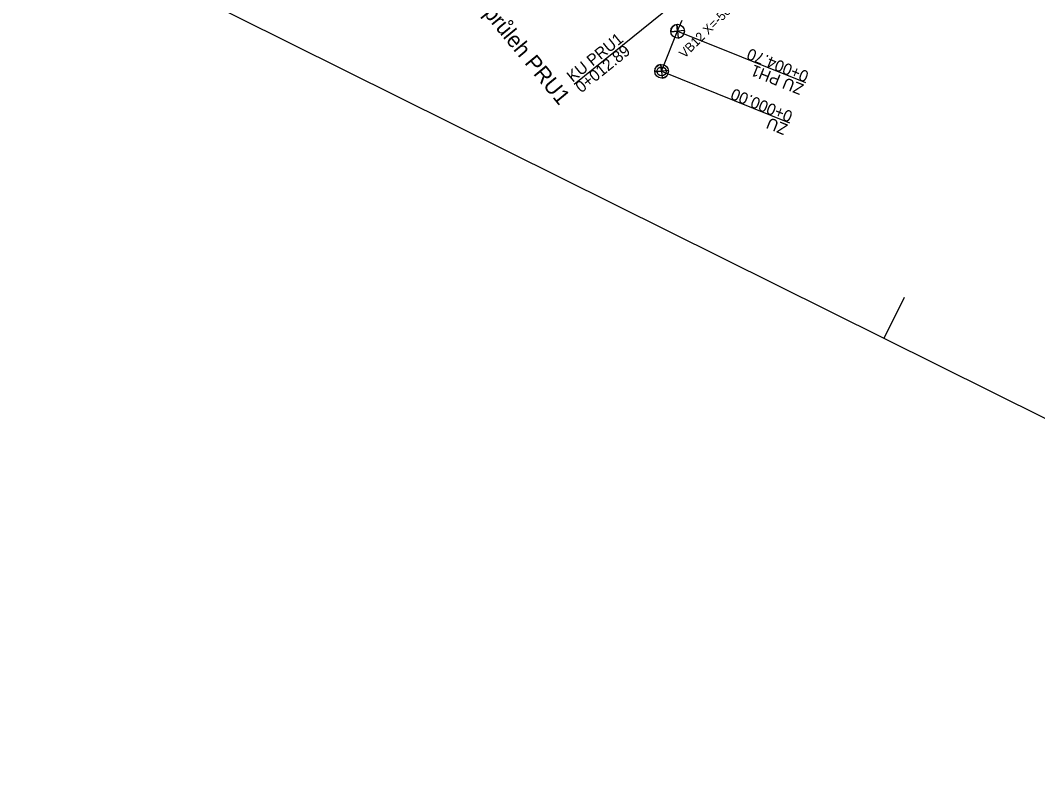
# Model space of a CAD drawing. Extents: x -564052 to -563798, y -1163587 to -1163361.
# Drawn here: x -564052.3 to -563941.5, y -1163587 to -1163505.7 of the extents above; entities that cross this region are included whole.
import ezdxf

# ---------------------------------------------------------------- set-up
doc = ezdxf.new("R2010")
doc.units = 0
for name, color, linetype in [('4', 7, 'Continuous'), ('_popis staničení PH1', 7, 'Continuous'), ('_popis staničení PRU1', 7, 'Continuous'), ('_rám C35', 7, 'Continuous'), ('_rám PH2 a PH4', 7, 'Continuous'), ('Default', 7, 'Continuous')]:
    doc.layers.add(name, color=color, linetype=linetype)

msp = doc.modelspace()

# ---------------------------------------------------------------- linework, layer by layer
msp.add_lwpolyline([(-563982.48, -1163511.21), (-563980.62, -1163506.57), (-563980.24, -1163505.64)])
at = {"layer": '_popis staničení PH1'}
for points in [[(-563980.73, -1163506.85), (-563966.81, -1163512.45)], [(-563982.48, -1163511.21), (-563968.57, -1163516.81)]]:
    msp.add_lwpolyline(points, dxfattribs=at)
msp.add_circle((-563982.48, -1163511.21), 0.5, dxfattribs=at)
at = {"layer": '_popis staničení PRU1'}
msp.add_lwpolyline([(-563980.36, -1163503.21), (-563992.01, -1163512.66)], dxfattribs=at)
at = {"layer": '_rám C35'}
for p, q in [((-563980.8, -1163506.1), (-563980.66, -1163507.6)), ((-563980.73, -1163506.85), (-563980.8, -1163506.1)), ((-563980.73, -1163506.85), (-563980.8, -1163506.1)), ((-563979.98, -1163506.78), (-563981.48, -1163506.92)), ((-563981.48, -1163506.92), (-563980.73, -1163506.85)), ((-563981.48, -1163506.92), (-563980.73, -1163506.85)), ((-563979.98, -1163506.78), (-563980.73, -1163506.85)), ((-563980.73, -1163506.85), (-563980.66, -1163507.6)), ((-563982.55, -1163510.46), (-563982.41, -1163511.96)), ((-563982.48, -1163511.21), (-563982.55, -1163510.46)), ((-563982.48, -1163511.21), (-563982.55, -1163510.46)), ((-563981.74, -1163511.14), (-563983.23, -1163511.28)), ((-563983.23, -1163511.28), (-563982.48, -1163511.21)), ((-563983.23, -1163511.28), (-563982.48, -1163511.21)), ((-563981.74, -1163511.14), (-563982.48, -1163511.21)), ((-563982.48, -1163511.21), (-563982.41, -1163511.96))]:
    msp.add_line(p, q, dxfattribs=at)
for centre in [(-563980.73, -1163506.85), (-563982.48, -1163511.21)]:
    msp.add_circle(centre, 0.75, dxfattribs=at)
for centre, start, end in [((-563980.73, -1163506.85), 95.3168, 185.3168), ((-563980.73, -1163506.85), 95.3168, 185.3168), ((-563980.73, -1163506.85), 275.3168, 5.3168), ((-563982.48, -1163511.21), 95.3168, 185.3168), ((-563982.48, -1163511.21), 95.3168, 185.3168), ((-563982.48, -1163511.21), 275.3168, 5.3168)]:
    msp.add_arc(centre, 0.75, start, end, dxfattribs=at)
at = {"layer": '_rám PH2 a PH4'}
msp.add_line((-563958.26, -1163540.28), (-563956.04, -1163535.8), dxfattribs=at)
msp.add_lwpolyline([(-564052.28, -1163493.53), (-563864.24, -1163587.02), (-563798.13, -1163454.05), (-563986.17, -1163360.56)], close=True, dxfattribs=at)

# ---------------------------------------------------------------- texts
at = {"layer": '4'}
msp.add_text('Odpadní průleh PRU1', height=1.7047, rotation=309.4887, dxfattribs=at).set_placement((-564007.87, -1163497.7))
at = {"layer": '_popis staničení PH1'}
for s, p in [('0+004.70', (-563966.35, -1163511.29)), ('ZU PH1 ', (-563966.91, -1163512.68)), ('0+000.00', (-563968.1, -1163515.65)), ('ZU ', (-563968.66, -1163517.04))]:
    msp.add_text(s, height=1.25, rotation=158.0764, dxfattribs=at).set_placement(p)
at = {"layer": '_popis staničení PRU1'}
for s, p in [('KU PRU1 ', (-563992.16, -1163512.47)), ('0+012.89', (-563991.22, -1163513.63))]:
    msp.add_text(s, height=1.25, rotation=39.0525, dxfattribs=at).set_placement(p)
at = {"layer": 'Default'}
msp.add_text('VB12 X=-563982.48,Y=-1163511.21', height=1, rotation=45, dxfattribs=at).set_placement((-563979.98, -1163509.86))

doc.saveas('drawing.dxf')
